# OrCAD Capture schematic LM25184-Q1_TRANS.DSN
size E; title: LM25184-Q1 42-VIN PSR Flyback DC/DC Converter with 65-V,; rev: 1.0; note: Datasheet: SNVSBJ6    EVM: SNVU680; note: Synchronous Step Down Converter
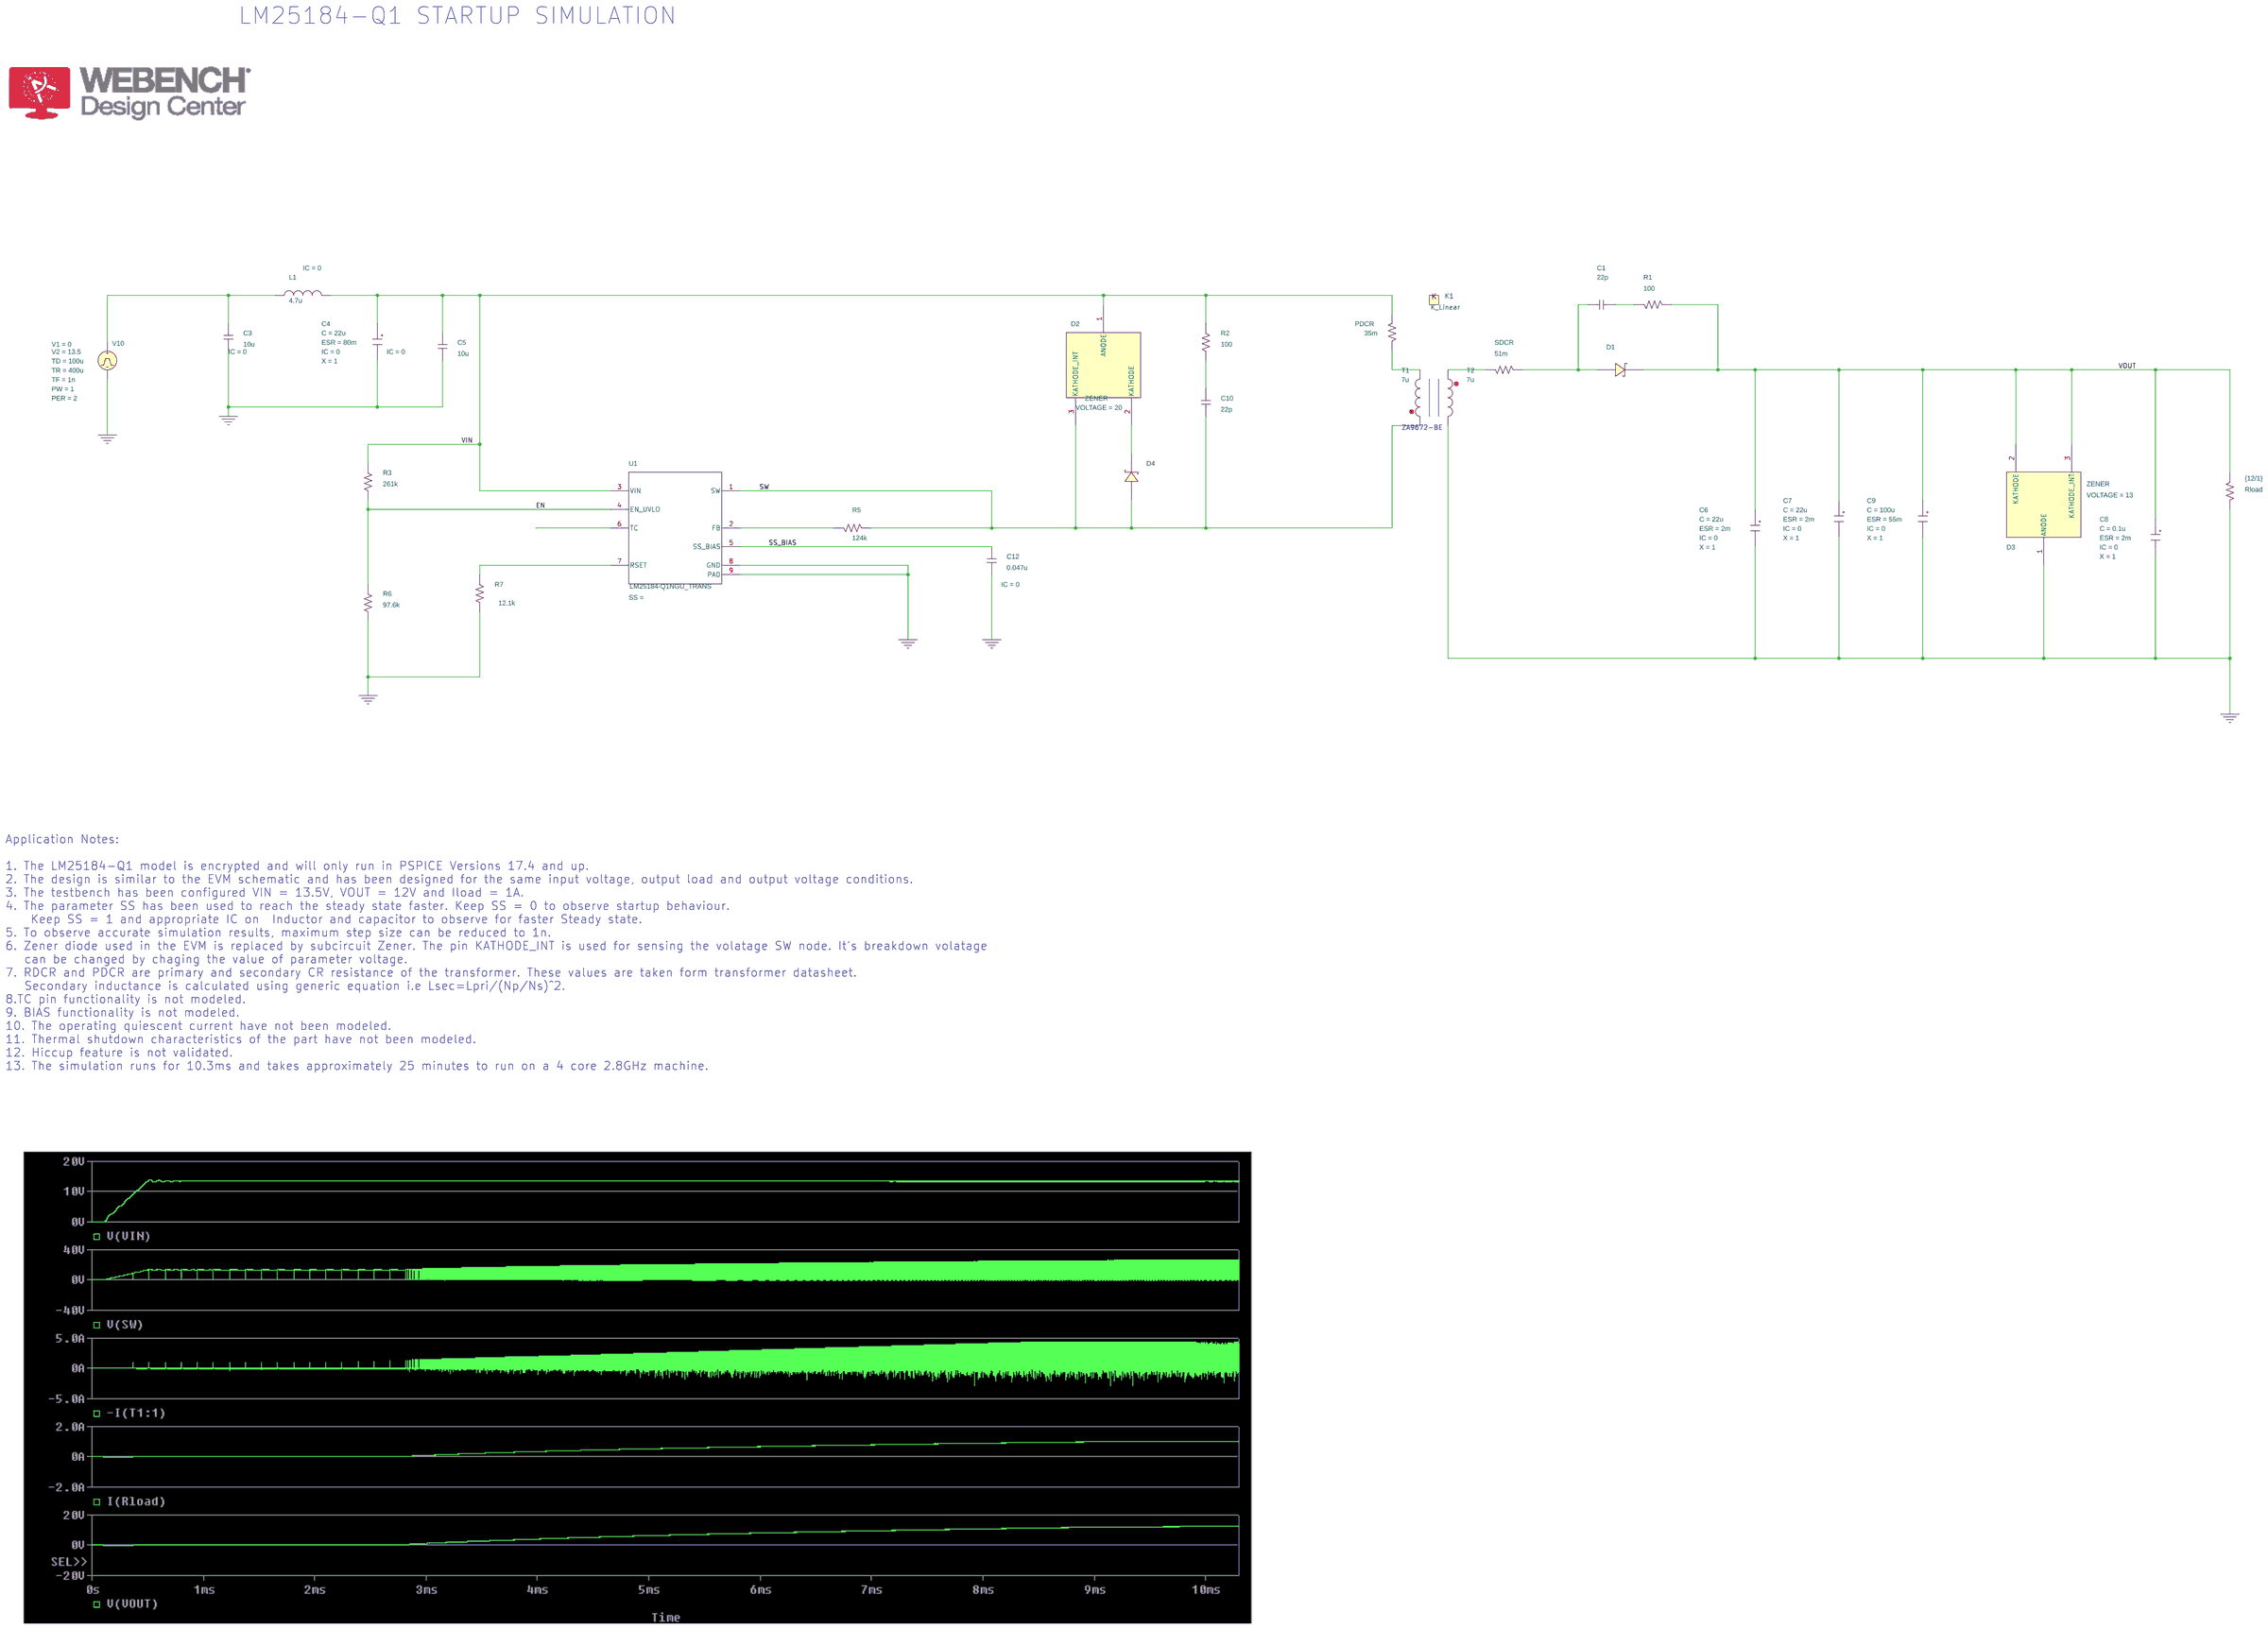
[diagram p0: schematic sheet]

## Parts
C1  22p  [RAD/CK05]
C3  10u  [RAD/CK05]
C4  CESR
C5  10u  [RAD/CK05]
C6  CESR
C7  CESR
C8  CESR
C9  CESR
C10  22p  [RAD/CK05]
C12  0.047u  [RAD/CK05]
D1  D_D
D2  ZENER
D3  ZENER
D4  D_D
K1  K_Linear
L1  4.7u  [DISC/.350x.175/LS.200x.100/.034]
PDCR  35m  [AX/RC05]
R1  100  [AX/RC05]
R2  100  [AX/RC05]
R3  261k  [AX/RC05]
R5  124k  [AX/RC05]
R6  97.6k  [AX/RC05]
R7  12.1k  [AX/RC05]
Rload  {12/1}  [AX/RC05]
SDCR  51m  [AX/RC05]
T1  7u  [DISC/.350x.175/LS.200x.100/.034]
T2  7u  [DISC/.350x.175/LS.200x.100/.034]
U1  LM25184-Q1NGU_TRANS  [NGU0008C]
V10  VPULSE

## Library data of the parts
C1 C10 = C
C3 C5 C12 = C: IC: 0
C4 = CESR_0: C: 22u; ESR: 80m; IC: 0; PSpiceTemplate: X^@REFDES %IN %OUT @MODEL PARAMS:  ?C|C=@C||C=100u|  ?ESR|ESR=@ESR||ESR=0.01| ?X|X=@X||X=2|  ?IC|IC=@IC||IC=2|; X: 1
C6 C7 = CESR_0: C: 22u; ESR: 2m; IC: 0; PSpiceTemplate: X^@REFDES %IN %OUT @MODEL PARAMS:  ?C|C=@C||C=100u|  ?ESR|ESR=@ESR||ESR=0.01| ?X|X=@X||X=2|  ?IC|IC=@IC||IC=2|; X: 1
C8 = CESR_0: C: 0.1u; ESR: 2m; IC: 0; PSpiceTemplate: X^@REFDES %IN %OUT @MODEL PARAMS:  ?C|C=@C||C=100u|  ?ESR|ESR=@ESR||ESR=0.01| ?X|X=@X||X=2|  ?IC|IC=@IC||IC=2|; X: 1
C9 = CESR_0: C: 100u; ESR: 55m; IC: 0; PSpiceTemplate: X^@REFDES %IN %OUT @MODEL PARAMS:  ?C|C=@C||C=100u|  ?ESR|ESR=@ESR||ESR=0.01| ?X|X=@X||X=2|  ?IC|IC=@IC||IC=2|; X: 1
D1 = D_D_2_1: PSpiceTemplate: D^@REFDES %1 %2 @MODEL
D2 = ZENER: VOLTAGE: 20
D3 = ZENER: VOLTAGE: 13
D4 = D_D_2: PSpiceTemplate: D^@REFDES %1 %2 @MODEL
K1 = K_Linear: COUPLING: 1; L1: T1; L2: T2
L1 = L_v2: IC: 0
PDCR R1-R3 R5-R7 Rload SDCR = R
T1 T2 = L
U1 = LM25184-Q1NGU_TRANS
V10 = VPULSE: PER: 2; PW: 1; TD: 100u; TF: 1n; TR: 400u; V1: 0; V2: 13.5

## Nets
VIN: C4.1(IN) C5.1 D2.1(ANODE) L1.2 PDCR.2 R2.1 R3.1 U1.3(VIN)
0: C3.2 C4.3(OUT) C5.2 C6.3(OUT) C7.3(OUT) C8.3(OUT) C9.3(OUT) C12.2 D3.1(ANODE) R6.2 R7.2 Rload.2 T2.2 U1.8(GND) U1.9(PAD) V10.2(-)
EN: R3.2 R6.1 U1.4(EN_UVLO)
SS_BIAS: C12.1 U1.5(SS_BIAS)
SW: C10.2 D2.3(KATHODE_INT) D4.1 R5.2 T1.1 U1.1(SW)
VOUT: C6.1(IN) C7.1(IN) C8.1(IN) C9.1(IN) D1.2 D3.2(KATHODE) D3.3(KATHODE_INT) R1.2 Rload.1
N16770337: C3.1 L1.1 V10.1(+)
N16770435: C10.1 R2.2
N16770603: C1.2 D1.1 SDCR.2
N16770613: C1.1 R1.1
N16777181: R7.1 U1.7(RSET)
N16781197: R5.1 U1.2(FB)
N16799169: D2.2(KATHODE) D4.2
N16804035: PDCR.1 T1.2
N16804051: SDCR.1 T2.1

Not connected (* = marked no-connect by the designer): U1 6(TC)

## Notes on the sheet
- LM25184-Q1 STARTUP SIMULATION
- ZA9672-BE
- Application Notes:
  1. The LM25184-Q1 model is encrypted and will only run in PSPICE Versions 17.4 and up.
  2. The design is similar to the EVM schematic and has been designed for the same input voltage, output load and output voltage conditions.
  3. The testbench has been configured VIN = 13.5V, VOUT = 12V and Iload = 1A.
  4. The parameter SS has been used to reach the steady state faster. Keep SS = 0 to observe startup behaviour.
      Keep SS = 1 and appropriate IC on  Inductor and capacitor to observe for faster Steady state.
  5. To observe accurate simulation results, maximum step size can be reduced to 1n.
  6. Zener diode used in the EVM is replaced by subcircuit Zener. The pin KATHODE_INT is used for sensing the volatage SW node. It's breakdown volatage
     can be changed by chaging the value of parameter voltage.
  7. RDCR and PDCR are primary and secondary CR resistance of the transformer. These values are taken form transformer datasheet.
     Secondary inductance is calculated using generic equation i.e Lsec=Lpri/(Np/Ns)^2.
  8.TC pin functionality is not modeled.
  9. BIAS functionality is not modeled.
  10. The operating quiescent current have not been modeled.
  11. Thermal shutdown characteristics of the part have not been modeled.
  12. Hiccup feature is not validated.
  13. The simulation runs for 10.3ms and takes approximately 25 minutes to run on a 4 core 2.8GHz machine.
